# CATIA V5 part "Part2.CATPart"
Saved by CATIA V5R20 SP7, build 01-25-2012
Part number: skl_bâti
Publications: "Axe_pivot_bâti_bras", "Axe_pivot_bâti_levier", "Plan.1"
Bounding box of the stored display mesh (mm): x 0 to 0, y -390 to 700, z 0 to 20
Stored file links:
  U:\IAO\thinkmotion catia2\Part2.CATPart
  U:\IAO\thinkmotion catia2\skl_862_adubourgno.CATProduct
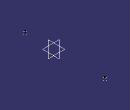
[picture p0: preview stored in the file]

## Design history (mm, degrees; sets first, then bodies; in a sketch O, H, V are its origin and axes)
Set1
  Plane1: linked copy from another document
  Point1 "A": linked copy from another document
  Point2 "C": linked copy from another document
Set2
  Line1 "Axe_pivot_bâti_levier": type Normal, RefPoint Point1, RefSkin Plane1, Start 0, End 20
  Line2 "Axe_pivot_bâti_bras": type Normal, RefPoint Point2, RefSkin Plane1, Start 0, End 20
Body1 (main body)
